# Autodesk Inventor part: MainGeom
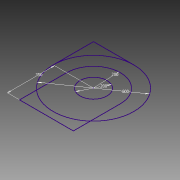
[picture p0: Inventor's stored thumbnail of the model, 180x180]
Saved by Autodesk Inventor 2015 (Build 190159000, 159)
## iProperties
Created: 2006-05
Part Number: MainGeom
Document SubType Name: Modeling
Designer: ricara
Density: 1 g/cm^3
Material: Generic
Appearance: Default
Author: ricara
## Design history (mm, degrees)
sketch "Sketch1"
  geometry: L1 (0, 300)-(-300, 300); L2 (-300, 0)-(-300, 300); L3 (-200, 0)-(-200, -350); L4 (-200, -350)-(200, -350); L5 (200, -350)-(200, 0); C1 r 100 at (0, 0); A1 r 300 centre (0, 0) between (0, 300) and (-300, 0); A2 r 200 centre (0, 0) between (200, 0) and (-200, 0); 1 further point
  constraints: 10 end point, 4 point on circle, 4 tangent, 3 centre point, 3 coincident, 3 perpendicular, 1 horizontal, 1 parallel
  dimensions: "d0" = 600 diameter of A1; "d1" = 200 radius of A2; "d2" = 200 diameter of C1; "d3" = 350 distance from line of point (0, 0) L4
